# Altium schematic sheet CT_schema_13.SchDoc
size 389 x 385 mm
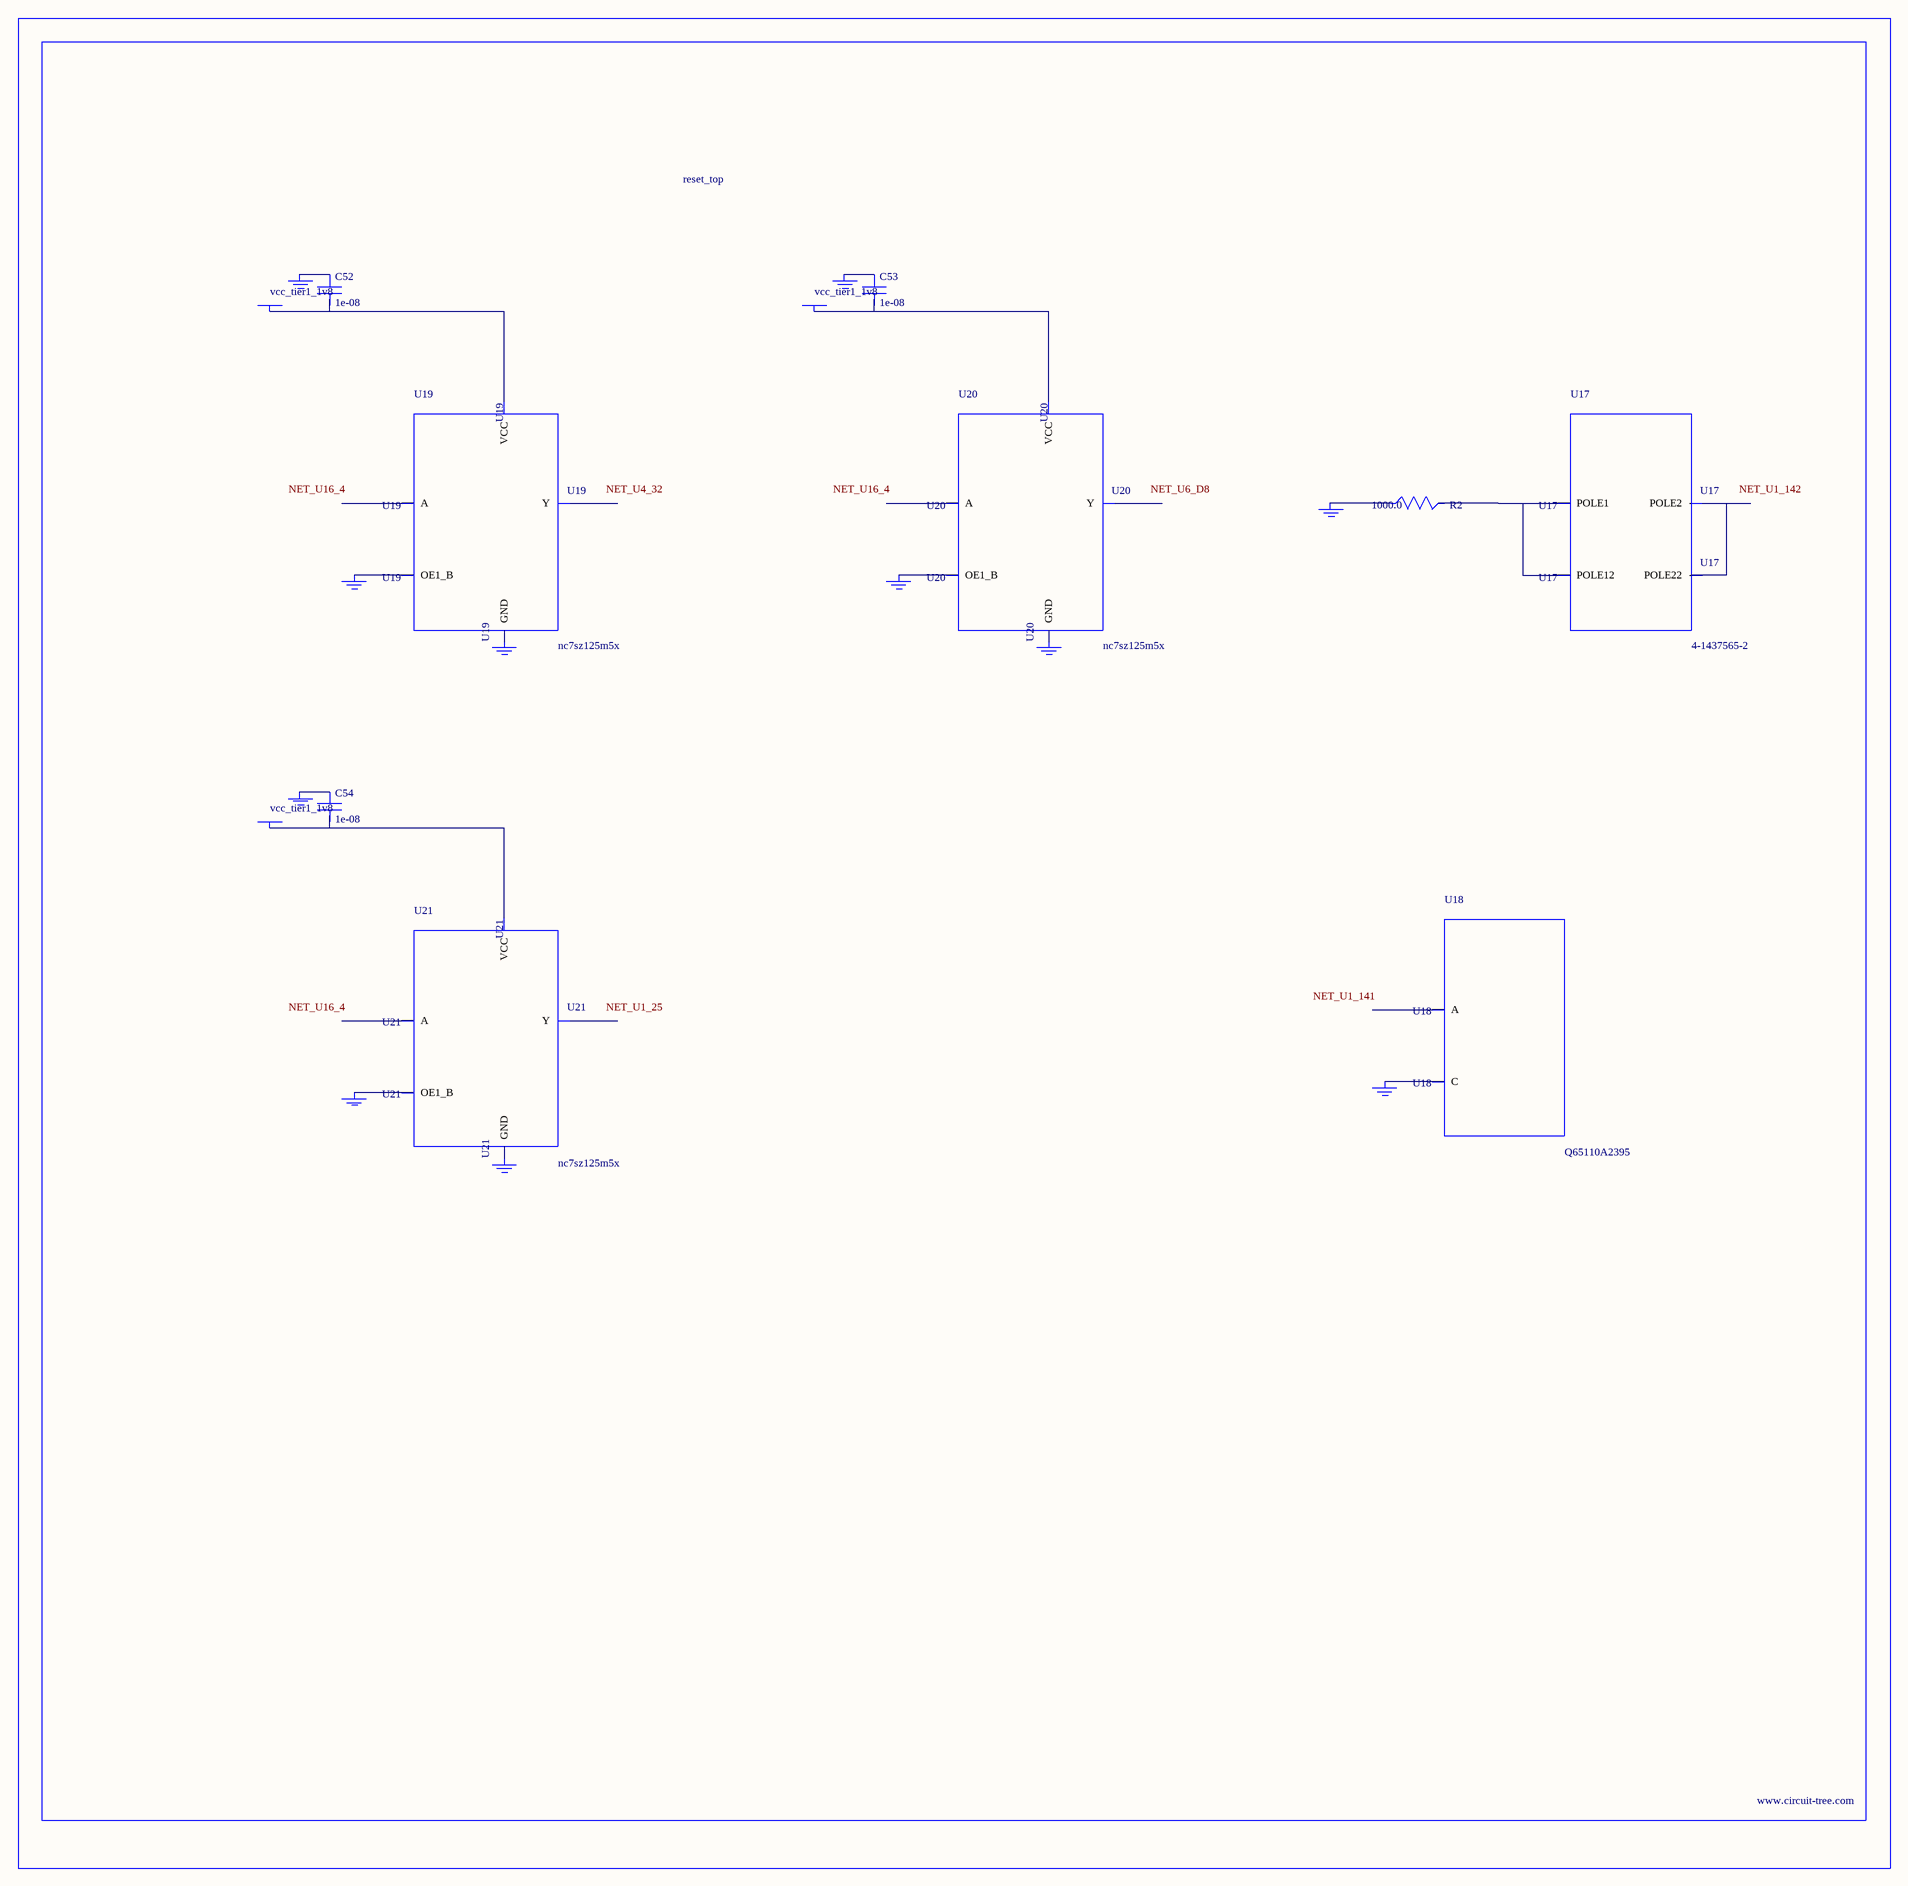
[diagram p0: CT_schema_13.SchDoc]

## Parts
BORDER12  (no value)
C52  1e-08  [C0402]
C53  1e-08  [C0402]
C54  1e-08  [C0402]
GND_INSTANCE_12_0  (no value)
GND_INSTANCE_12_1  (no value)
GND_INSTANCE_12_2  (no value)
GND_INSTANCE_12_3  (no value)
GND_INSTANCE_12_4  (no value)
GND_INSTANCE_12_5  (no value)
GND_INSTANCE_12_6  (no value)
GND_INSTANCE_12_7  (no value)
GND_INSTANCE_12_8  (no value)
GND_INSTANCE_12_9  (no value)
GND_INSTANCE_12_10  (no value)
POWER_INSTANCE_12_0  vcc_tier1_1v8
POWER_INSTANCE_12_1  vcc_tier1_1v8
POWER_INSTANCE_12_2  vcc_tier1_1v8
R2  1000.0  [R0603]
U17  4-1437565-2  [SW_4-1437565-2]
U18  Q65110A2395  [LGM67K-G1J2-24-Z]
U19  nc7sz125m5x  [NC7SZ125M5X]
U20  nc7sz125m5x  [NC7SZ125M5X]
U21  nc7sz125m5x  [NC7SZ125M5X]

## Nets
NetC52_1: C52.1 GND_INSTANCE_12_2.0(GND)
NetC52_2: C52.2 POWER_INSTANCE_12_0.0(PWR) U19.5(VCC)
NetC53_1: C53.1 GND_INSTANCE_12_5.0(GND)
NetC53_2: C53.2 POWER_INSTANCE_12_1.0(PWR) U20.5(VCC)
NetC54_1: C54.1 GND_INSTANCE_12_8.0(GND)
NetC54_2: C54.2 POWER_INSTANCE_12_2.0(PWR) U21.5(VCC)
NetGND_INSTANCE_12_0_0: GND_INSTANCE_12_0.0(GND) R2.1
NetGND_INSTANCE_12_1_0: GND_INSTANCE_12_1.0(GND) U18.C
NetGND_INSTANCE_12_3_0: GND_INSTANCE_12_3.0(GND) U19.1(OE1_B)
NetGND_INSTANCE_12_4_0: GND_INSTANCE_12_4.0(GND) U19.3(GND)
NetGND_INSTANCE_12_6_0: GND_INSTANCE_12_6.0(GND) U20.1(OE1_B)
NetGND_INSTANCE_12_7_0: GND_INSTANCE_12_7.0(GND) U20.3(GND)
NetGND_INSTANCE_12_9_0: GND_INSTANCE_12_9.0(GND) U21.1(OE1_B)
NetGND_INSTANCE_12_10_0: GND_INSTANCE_12_10.0(GND) U21.3(GND)
NetR2_2: R2.2 U17.1(POLE1) U17.2(POLE12)
NetU17_3: U17.3(POLE2) U17.4(POLE22)

Not connected (* = marked no-connect by the designer): U18 A; U19 2(A) 4(Y); U20 2(A) 4(Y); U21 2(A) 4(Y)

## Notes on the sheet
- Labels drawn without touching a wire or pin: NET_U1_25, NET_U1_141, NET_U1_142, NET_U4_32, NET_U6_D8, NET_U16_4

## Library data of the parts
BORDER12 = BORDER_PAGE12
C52-C54 = C0402C103K3RAC
GND_INSTANCE_12_0-GND_INSTANCE_12_10 = GND
POWER_INSTANCE_12_0-POWER_INSTANCE_12_2 = PWR
R2 = RC0603JR-071KL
